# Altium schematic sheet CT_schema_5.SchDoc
size 399 x 269 mm
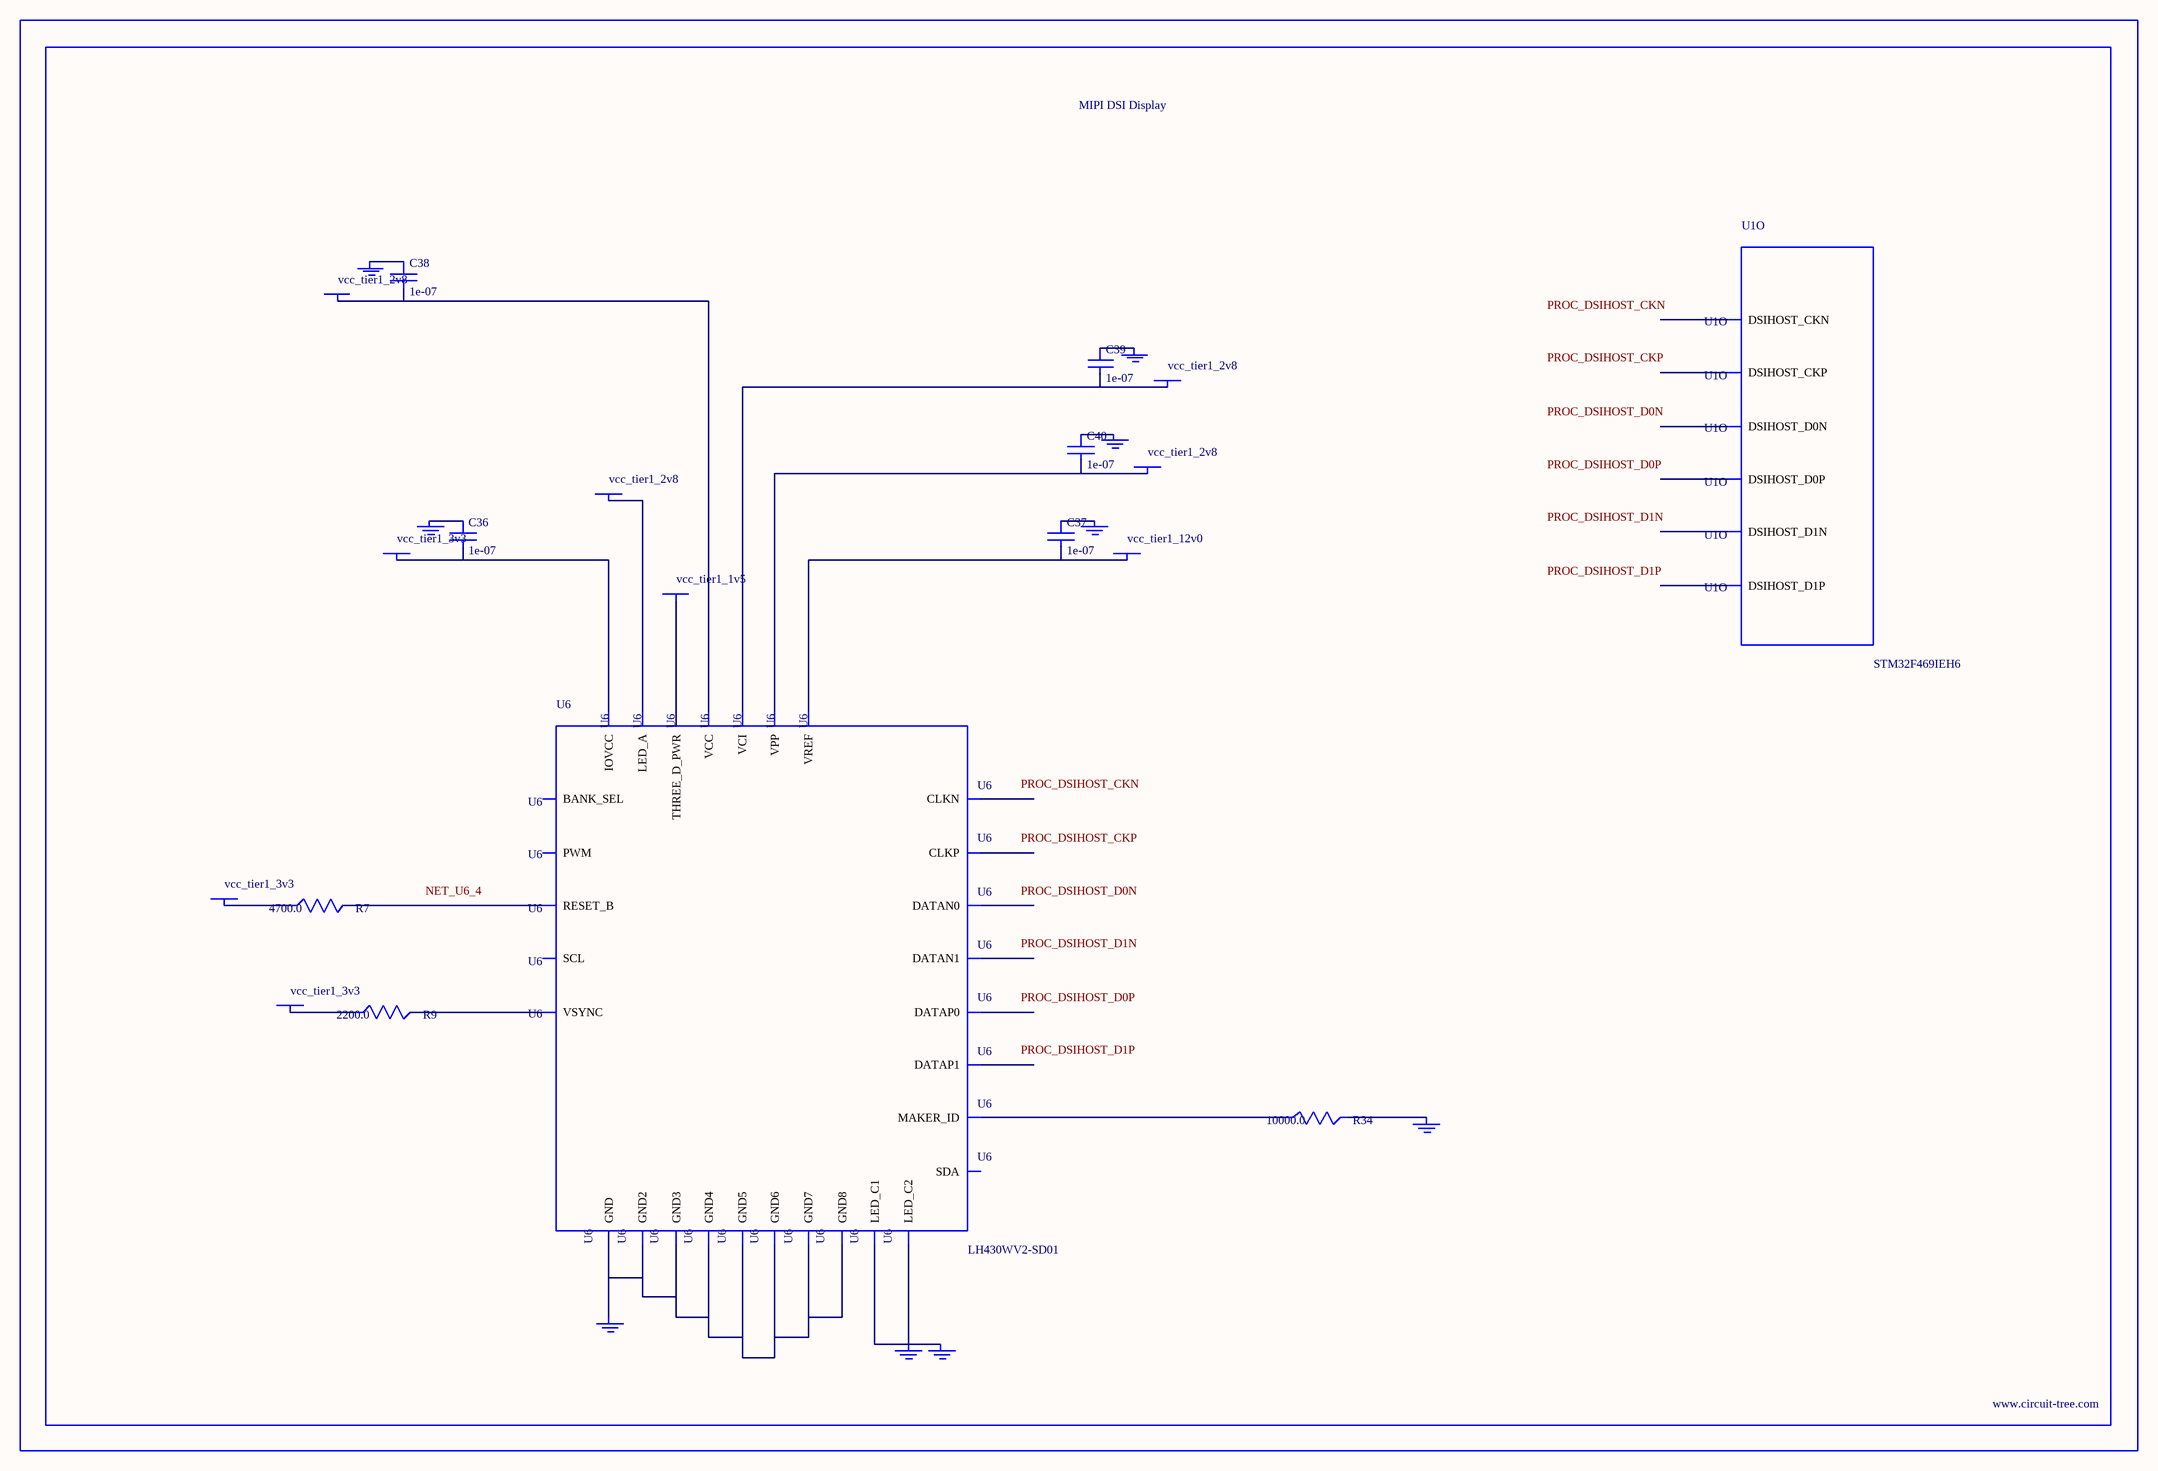
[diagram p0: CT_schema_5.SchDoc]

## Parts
BORDER4  (no value)
C36  1e-07  [C0402]
C37  1e-07  [C0402]
C38  1e-07  [C0402]
C39  1e-07  [C0402]
C40  1e-07  [C0402]
GND_INSTANCE_4_0  (no value)
GND_INSTANCE_4_1  (no value)
GND_INSTANCE_4_2  (no value)
GND_INSTANCE_4_3  (no value)
GND_INSTANCE_4_4  (no value)
GND_INSTANCE_4_5  (no value)
GND_INSTANCE_4_6  (no value)
GND_INSTANCE_4_7  (no value)
GND_INSTANCE_4_8  (no value)
POWER_INSTANCE_4_0  vcc_tier1_3v3
POWER_INSTANCE_4_1  vcc_tier1_2v8
POWER_INSTANCE_4_2  vcc_tier1_2v8
POWER_INSTANCE_4_3  vcc_tier1_2v8
POWER_INSTANCE_4_4  vcc_tier1_2v8
POWER_INSTANCE_4_5  vcc_tier1_12v0
POWER_INSTANCE_4_6  vcc_tier1_3v3
POWER_INSTANCE_4_7  vcc_tier1_3v3
POWER_INSTANCE_4_8  vcc_tier1_1v5
R7  4700.0  [R0603]
R9  2200.0  [R0603]
R34  10000.0  [R0603]
U1  STM32F469IEH6  [UFBGA176]  (part O of 16)
U6  LH430WV2-SD01  [LH430WV2-SD01]

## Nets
NetC36_1: C36.1 GND_INSTANCE_4_0.0(GND)
NetC36_2: C36.2 POWER_INSTANCE_4_0.0(PWR) U6.2(IOVCC)
NetC37_1: C37.1 GND_INSTANCE_4_7.0(GND)
NetC37_2: C37.2 POWER_INSTANCE_4_5.0(PWR) U6.30(VREF)
NetC38_1: C38.1 GND_INSTANCE_4_5.0(GND)
NetC38_2: C38.2 POWER_INSTANCE_4_3.0(PWR) U6.22(VCC)
NetC39_1: C39.1 GND_INSTANCE_4_4.0(GND)
NetC39_2: C39.2 POWER_INSTANCE_4_2.0(PWR) U6.21(VCI)
NetC40_1: C40.1 GND_INSTANCE_4_6.0(GND)
NetC40_2: C40.2 POWER_INSTANCE_4_4.0(PWR) U6.23(VPP)
NetGND_INSTANCE_4_1_0: GND_INSTANCE_4_1.0(GND) GND_INSTANCE_4_2.0(GND) U6.17(LED_C1) U6.18(LED_C2)
NetGND_INSTANCE_4_3_0: GND_INSTANCE_4_3.0(GND) R34.2
NetGND_INSTANCE_4_8_0: GND_INSTANCE_4_8.0(GND) U6.1(GND) U6.6(GND2) U6.9(GND3) U6.12(GND4) U6.15(GND5) U6.19(GND6) U6.24(GND7) U6.27(GND8)
NetPOWER_INSTANCE_4_1_0: POWER_INSTANCE_4_1.0(PWR) U6.16(LED_A)
NetPOWER_INSTANCE_4_6_0: POWER_INSTANCE_4_6.0(PWR) R7.1
NetPOWER_INSTANCE_4_7_0: POWER_INSTANCE_4_7.0(PWR) R9.1
NetPOWER_INSTANCE_4_8_0: POWER_INSTANCE_4_8.0(PWR) U6.29(THREE_D_PWR)
NetR7_2: R7.2 U6.4(RESET_B)
NetR9_2: R9.2 U6.5(VSYNC)
NetR34_1: R34.1 U6.20(MAKER_ID)

Not connected (* = marked no-connect by the designer): U1 E12(DSIHOST_D1P) E13(DSIHOST_D1N) L12(DSIHOST_CKP) L13(DSIHOST_CKN) M12(DSIHOST_D0P) M13(DSIHOST_D0N); U6 3(PWM) 7(DATAN0) 8(DATAP0) 10(DATAN1) 11(DATAP1) 13(CLKN) 14(CLKP) 25(SCL) 26(SDA) 28(BANK_SEL)

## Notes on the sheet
- Labels drawn without touching a wire or pin: NET_U6_4, PROC_DSIHOST_CKN, PROC_DSIHOST_CKP, PROC_DSIHOST_D0N, PROC_DSIHOST_D0P, PROC_DSIHOST_D1N, PROC_DSIHOST_D1P

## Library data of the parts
BORDER4 = BORDER_PAGE4
C36-C40 = C0402C104K3RACTU
GND_INSTANCE_4_0-GND_INSTANCE_4_8 = GND
POWER_INSTANCE_4_0-POWER_INSTANCE_4_8 = PWR
R7 = RC0603JR-074K7L
R9 = RC0603JR-072K2L
R34 = RC0603JR-0710KL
